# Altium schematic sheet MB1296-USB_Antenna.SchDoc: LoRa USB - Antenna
size A4; Date: 18-AUG-2016; Organization: STMicroelectronics; Address1: Microcontrollers Division; Address2: 190, avenue Célestin COQ; Address3: 13106 ROUSSET Cedex; Address4: FRANCE; DocumentNumber: MB1296; Revision: C-01; SheetNumber: 5; SheetTotal: 6; Project: STM32 LoRa Discovery
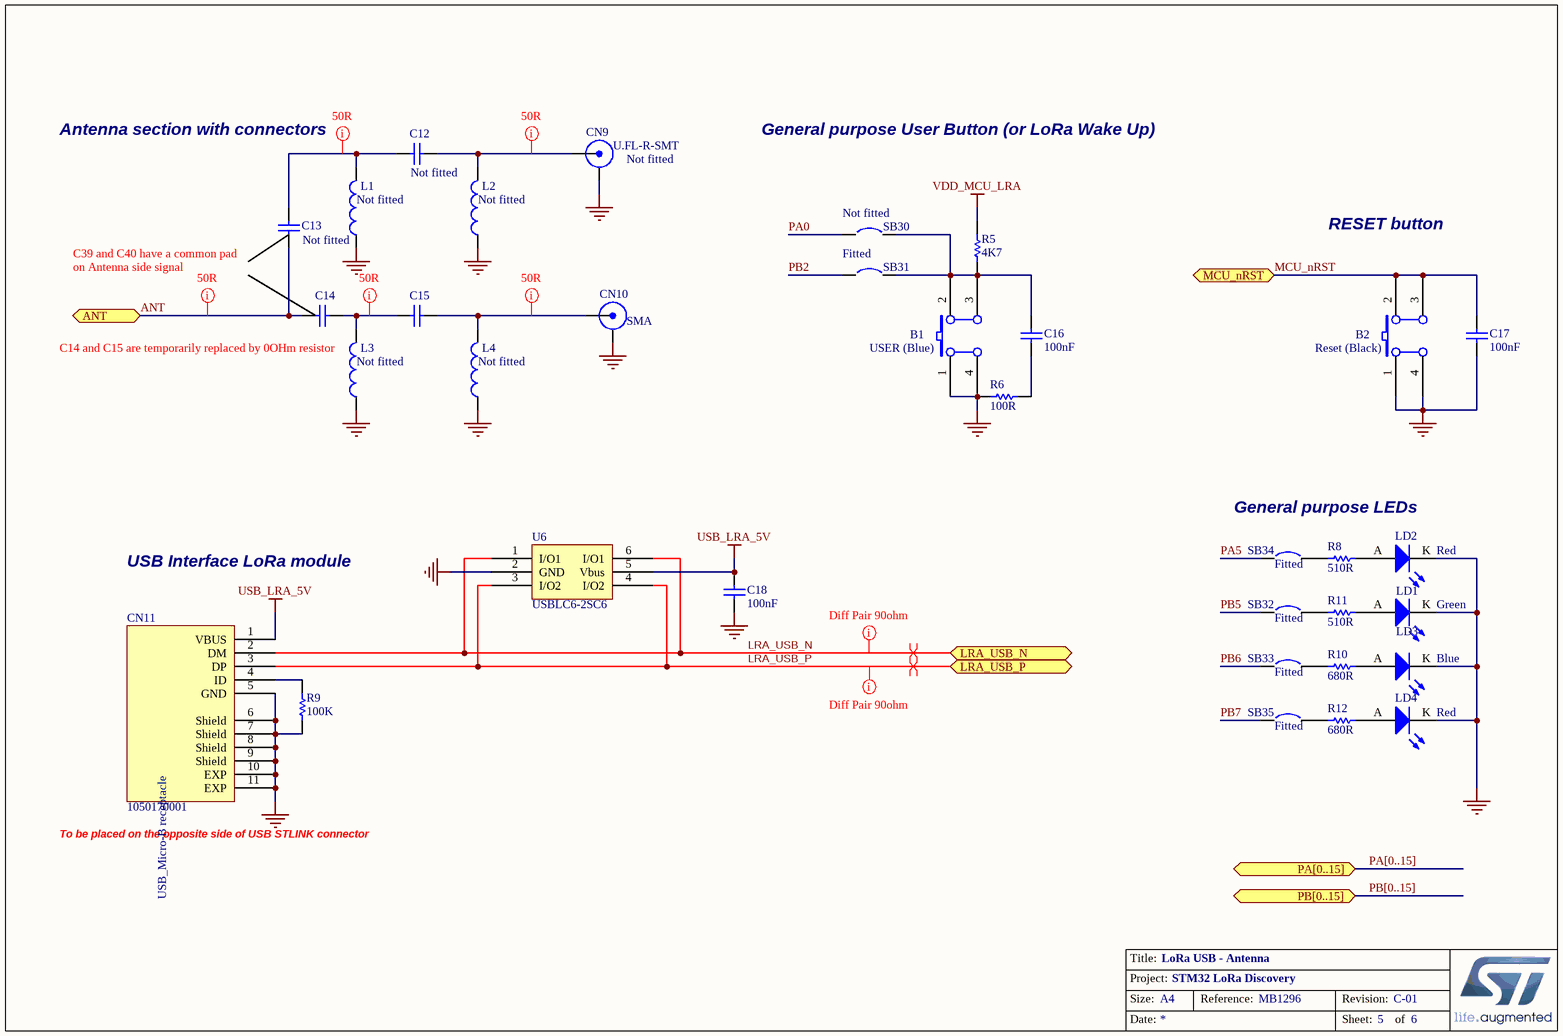
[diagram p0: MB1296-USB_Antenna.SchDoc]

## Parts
B1  USER (Blue)  [PB10]
B2  Reset (Black)  [PB10]
C12  (no value)  [0402]
C13  (no value)  [0402]
C14  (no value)  [0402]
C15  (no value)  [0402]
C16  100nF  [0603C]
C17  100nF  [0603C]
C18  100nF  [0603C]
CN9  U.FL-R-SMT  [UFL-SMD]
CN10  SMA  [SMA_COMBO_B]
CN11  1050170001  [Molex_1050170001]
L1  (no value)  [0402]
L2  (no value)  [0402]
L3  (no value)  [0402]
L4  (no value)  [0402]
LD1  Green  [0603D]
LD2  Red  [0603D]
LD3  Blue  [0603D]
LD4  Red  [0603D]
R5  4K7  [0603R]
R6  100R  [0603R]
R8  510R  [0603R]
R9  100K  [0603]
R10  680R  [0603R]
R11  510R  [0603R]
R12  680R  [0603R]
SB30  Circuit Breaker  [JP2_SMD]  (value not drawn)
SB31  Circuit Breaker  [JP2_SMD]  (value not drawn)
SB32  Circuit Breaker  [JP2_SMD]  (value not drawn)
SB33  Circuit Breaker  [JP2_SMD]  (value not drawn)
SB34  Circuit Breaker  [JP2_SMD]  (value not drawn)
SB35  Circuit Breaker  [JP2_SMD]  (value not drawn)
U6  USBLC6-2SC6  [SOT23-6L]

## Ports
ANT, LRA_USB_N, LRA_USB_P, MCU_nRST, PA[0..15] (bidir), PB[0..15] (bidir)

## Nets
GND: B1.1(A0) B1.4(A1) B2.1(A0) B2.4(A1) C17.1 C18.1 CN9.2(Y) CN10.2(Y) CN11.5(GND) CN11.6(Shield) CN11.7(Shield) CN11.8(Shield) CN11.9(Shield) CN11.10(EXP) CN11.11(EXP) L1.1 L2.1 L3.1 L4.1 LD1.K LD2.K LD3.K LD4.K R6.2 R9.1 U6.2(GND)
USB_LRA_5V: C18.2 CN11.1(VBUS) U6.5(Vbus)
VDD_MCU_LRA: R5.2
ANT: C13.2 C14.1 ; port ANT
LRA_USB_N: CN11.2(DM) U6.1(I/O1) U6.6(I/O1) ; port LRA_USB_N
LRA_USB_P: CN11.3(DP) U6.3(I/O2) U6.4(I/O2) ; port LRA_USB_P
MCU_nRST: B2.2(B0) B2.3(B1) C17.2 ; port MCU_nRST
PA0: SB30.1
PA5: SB34.1
PB2: SB31.1
PB5: SB32.1
PB6: SB33.1
PB7: SB35.1
NetB1_2: B1.2(B0) B1.3(B1) C16.2 R5.1 SB30.2 SB31.2
NetC12_1: C12.1 C13.1 L1.2
NetC12_2: C12.2 CN9.1(X) L2.2
NetC14_2: C14.2 C15.1 L3.2
NetC15_2: C15.2 CN10.1(X) L4.2
NetC16_1: C16.1 R6.1
NetCN11_4: CN11.4(ID) R9.2
NetLD1_A: LD1.A R11.2
NetLD2_A: LD2.A R8.2
NetLD3_A: LD3.A R10.2
NetLD4_A: LD4.A R12.2
NetR8_1: R8.1 SB34.2
NetR10_1: R10.1 SB33.2
NetR11_1: R11.1 SB32.2
NetR12_1: R12.1 SB35.2

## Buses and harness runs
bus PA[0..15] = port PA[0..15]
bus PB[0..15] = port PB[0..15]

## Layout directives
mark named Diff Pair 90ohm: LRA_USB_N, LRA_USB_P
differential pair: LRA_USB_N, LRA_USB_P
net class 50R; rule Clearance Constraint [Clearance = 6.2mil]: ANT, NetC12_1, NetC12_2, NetC14_2, NetC15_2

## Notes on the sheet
- Antenna section with connectors
- Not fitted
- (near CN9) Not fitted
- General purpose User Button (or LoRa Wake Up)
- (near L1) Not fitted
- (near L2) Not fitted
- (near SB30) Not fitted
- RESET button
- (near C13) C39 and C40 have a common pad
- on Antenna side signal
- Fitted
- (near L3) C14 and C15 are temporarily replaced by 0OHm resistor
- (near L3) Not fitted
- (near L4) Not fitted
- General purpose LEDs
- USB Interface LoRa module
- (near SB34) Fitted
- (near SB32) Fitted
- (near SB33) Fitted
- (near SB35) Fitted
- (near CN11) To be placed on the opposite side of USB STLINK connector

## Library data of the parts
B1 = SW PUSHBUTTON: SE PUSHBUTTON; Manufacturer: wealthmetal; Manufacturer P/N: TD0341X-G01-BLU; Provided by: Subcon
B2 = SW PUSHBUTTON: SE PUSHBUTTON; Manufacturer: wealthmetal; Manufacturer P/N: TD0341X-G01-BLA; Provided by: Subcon
C12 C13 = CAP SMD 0402 NPO 18PF 16V 5%: 0402; Fitted: No
C14 C15 = CAP SMD 0402 NPO 18PF 16V 5%: 0402; Fitted: Yes 0Ohm resistor
C16-C18 = CAP: Capacitor 100nF; Manufacturer: YAGEO; Manufacturer P/N: CC0603KRX7R9BB104; Provided by: Subcon
CN9 = UFL
CN11 = 1050170001: Silkscreen: USB
L1-L4 = BLM15HG102SN1D: Fitted: No
LD1-LD4 = LED2: Typical RED, GREEN, YELLOW, AMBER GaAs LED; Manufacturer: Everlight; Manufacturer P/N  Green: 19-213SY6C/S530-E2/TR8LED; Manufacturer P/N  Red: 19-213-R6C-AP1Q2B-3T
R5 = res1_4: Resistor; Manufacturer: YAGEO; Manufacturer P/N: RC0603FR-074K7L; Provided by: Subcon
R6 = res1_4: Resistor; Manufacturer: YAGEO; Manufacturer P/N: RC0603FR-07100RL; Provided by: Subcon
R8 R11 = res1_4: Resistor; Manufacturer: YAGEO; Manufacturer P/N: RC0603FR-07510RL; Provided by: Subcon
R9 = RES SMD 0603 100K 75V 5% 0.1W: 0603 100K 75V 5% 0.1W; Manufacturer: YAGEO; Manufacturer P/N: RC0603FR-07100KL; Provided by: Subcon
R10 R12 = res1_4: Resistor; Manufacturer: YAGEO; Manufacturer P/N: RC0603FR-07680RL; Provided by: Subcon
SB30 = Circuit Breaker: Fitted: No
SB31-SB35 = Circuit Breaker: Fitted: Yes
U6 = USBLC6-2SC6: Manufacturer: STMicroelectronics; Manufacturer P/N: USBLC6-4SC6; ECCN_US/UE: EAR99/NEC; Provided by: STM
